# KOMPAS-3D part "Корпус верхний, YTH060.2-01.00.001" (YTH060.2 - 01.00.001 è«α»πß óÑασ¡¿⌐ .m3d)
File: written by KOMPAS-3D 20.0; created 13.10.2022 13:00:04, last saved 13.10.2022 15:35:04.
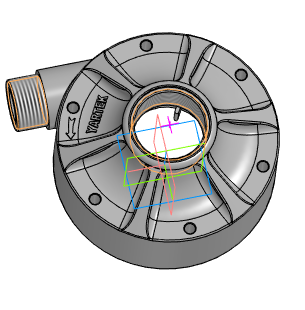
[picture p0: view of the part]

Document properties: Автор: Пользователь Windows; Полное имя файла: D:\информация пользователя\Desktop\ШОРОХ 2022\Насос ХИМия\YTH060.2 С торцевым уплотнением\3D  модель\YTH060.2 Насос сторцевым уплотнением\YTH060.2 - 01.00.001 Корпус верхний .m3d

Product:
- Part/product: Корпус верхний  | designation YTH060.2-01.00.001
    Материал: Полипропилен 21015 ГОСТ 26996-86 (density 900 kg/m3)
    Масса: 0.422296
  - Body: Тело 1
      Масса: 0.422361

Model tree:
1. Операция без истории:1  (labels: 22-0602 Крышка корпуса ЯРТЕХ)
2. Эскиз:1  (with: Операция без истории:1)
3. Элемент выдавливания:1
     Расстояние 2 = 89
4. Эскиз:2  (with: Операция без истории:1)
5. Элемент выдавливания:2  (with: Операция без истории:1)
     Расстояние 2 = 34
6. Эскиз:3  (with: Операция без истории:1)
7. Элемент выдавливания:3
     Расстояние 2 = 90; Угол 2 = 4
8. Фаска:1  (with: Операция без истории:1)
     Угол = 45; Длина 1 = 0.5; Длина 2 = 0.5
9. Скругление:1  (with: Операция без истории:1)
     Радиус = 1
10. Эскиз:4  (with: Операция без истории:1)
11. Сечение:1
12. Скругление:2  (with: Элемент выдавливания:3)
     Радиус = 0.2
13. Фаска:2  (with: Элемент выдавливания:3)
     Угол = 45; Длина 1 = 1; Длина 2 = 1
14. Фаска:3  (with: Операция без истории:1)
     Угол = 45; Длина 1 = 0.5; Длина 2 = 0.5
15. Элемент выдавливания:4  (with: Операция без истории:1)
     Расстояние 2 = 0.94
16. Условное изображение резьбы:2  (with: Операция без истории:1)  (labels: G 1)
     Длина резьбы = 20; Шаг резьбы = 2.309; Номинальный диаметр резьбы = 33.249
17. Подгонка:2  (with: Операция без истории:1)
18. Эскиз:6  (with: Операция без истории:1)
19. Элемент выдавливания:5  (with: Операция без истории:1)
     Расстояние 1 = 24.9737
20. Эскиз:7  (with: Операция без истории:1)
21. Отверстие:3  (with: Операция без истории:1)
     Глубина выреза = 25; Диаметр отверстия = 44.846; Угол конуса дна = 118
22. G 1.1/2  (with: Операция без истории:1)
     Длина резьбы = 25; Шаг резьбы = 2.309; Номинальный диаметр резьбы = 47.803
23. Фаска:4  (with: Отверстие:3)  (labels: Полипропилен 21015 ГОСТ 26996-86)
     Угол = 45; Длина 1 = 1; Длина 2 = 1

Expressions: 22-0602 Крышка корпуса ЯРТЕХ v10; cil2_6357-81
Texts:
  Точка начала. Х
  Точка начала. Y
  Точка начала. Z
  YTH060.2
